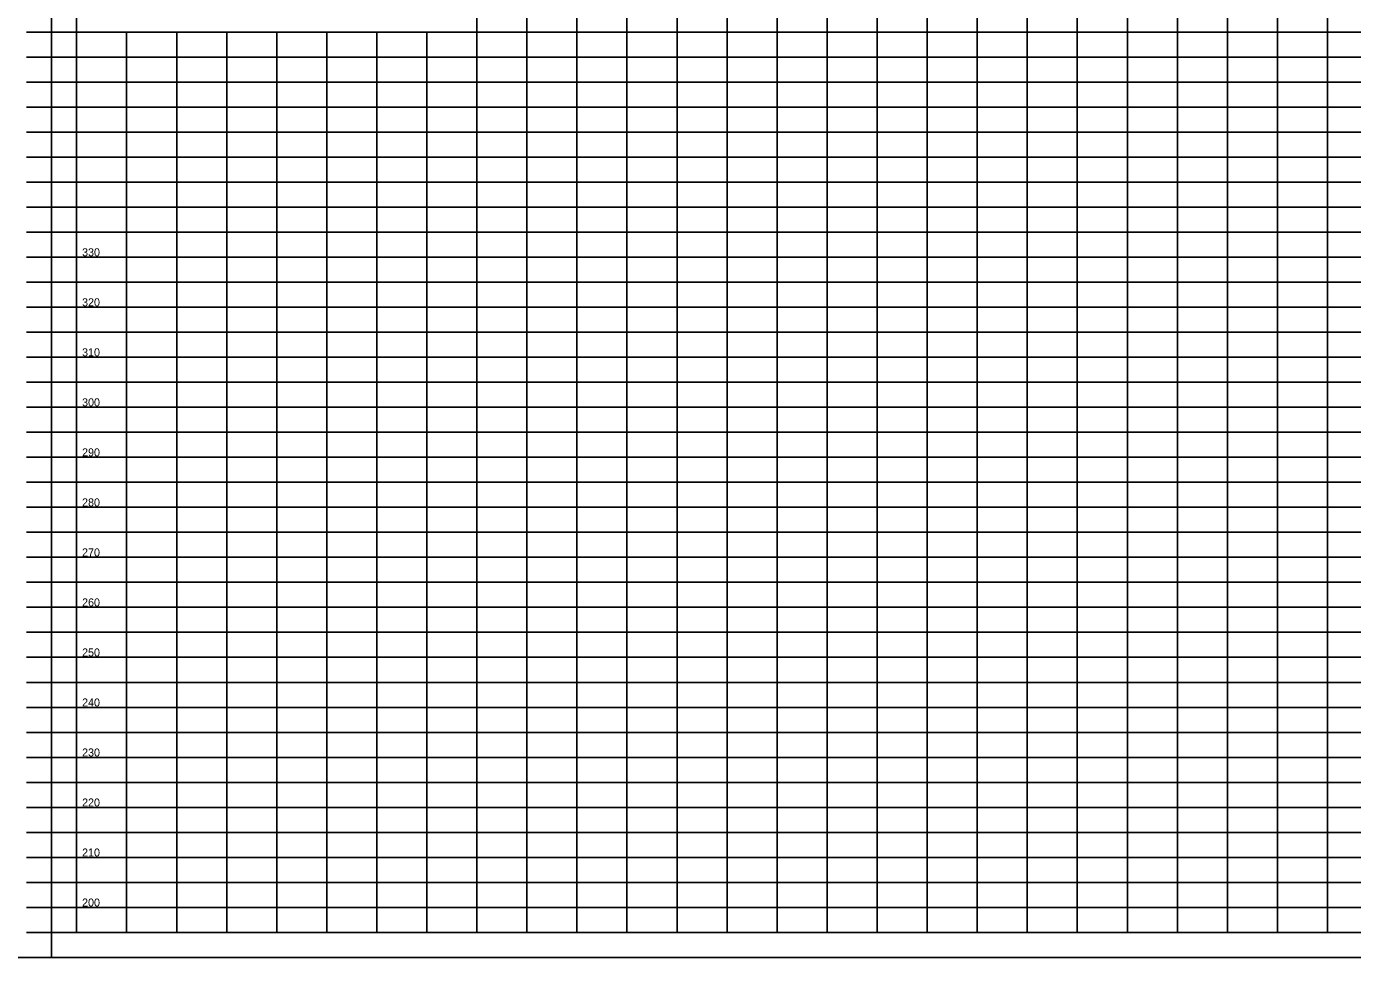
# Model space of a CAD drawing. Extents: x 1914168 to 1925341, y 720939 to 777401.
# Drawn here: x 1919832 to 1921157, y 735939 to 736870 of the extents above; entities that cross this region are included whole.
import ezdxf

# ---------------------------------------------------------------- set-up
doc = ezdxf.new("R2010")
doc.units = 0
for name, color, linetype in [('RD_DDB_ElevTX', 7, 'Continuous'), ('RD_PD_WallFill', 7, 'Continuous'), ('RD_SHT_IplotShp', 7, 'Continuous')]:
    doc.layers.add(name, color=color, linetype=linetype)

msp = doc.modelspace()

# ---------------------------------------------------------------- linework, layer by layer
at = {"layer": 'RD_PD_WallFill'}
for p, q in [((1919881.8, 735964.2), (1919881.8, 737014.2)), ((1919881.8, 735964.2), (1919881.8, 737014.2)), ((1920281.8, 735964.2), (1920281.8, 737014.2)), ((1920281.8, 735964.2), (1920281.8, 737014.2)), ((1920331.8, 735964.2), (1920331.8, 737014.2)), ((1920331.8, 735964.2), (1920331.8, 737014.2)), ((1920381.8, 735964.2), (1920381.8, 737014.2)), ((1920381.8, 735964.2), (1920381.8, 737014.2)), ((1920431.8, 735964.2), (1920431.8, 737014.2)), ((1920431.8, 735964.2), (1920431.8, 737014.2)), ((1920481.8, 735964.2), (1920481.8, 737014.2)), ((1920481.8, 735964.2), (1920481.8, 737014.2)), ((1920531.8, 735964.2), (1920531.8, 737014.2)), ((1920531.8, 735964.2), (1920531.8, 737014.2)), ((1920581.8, 735964.2), (1920581.8, 737014.2)), ((1920581.8, 735964.2), (1920581.8, 737014.2)), ((1920631.8, 735964.2), (1920631.8, 737014.2)), ((1920631.8, 735964.2), (1920631.8, 737014.2)), ((1920681.8, 735964.2), (1920681.8, 737014.2)), ((1920681.8, 735964.2), (1920681.8, 737014.2)), ((1920731.8, 735964.2), (1920731.8, 737014.2)), ((1920731.8, 735964.2), (1920731.8, 737014.2)), ((1920781.8, 735964.2), (1920781.8, 737014.2)), ((1920781.8, 735964.2), (1920781.8, 737014.2)), ((1920831.8, 735964.2), (1920831.8, 737014.2)), ((1920831.8, 735964.2), (1920831.8, 737014.2)), ((1920881.8, 735964.2), (1920881.8, 737014.2)), ((1920881.8, 735964.2), (1920881.8, 737014.2)), ((1920931.8, 735964.2), (1920931.8, 737014.2)), ((1920931.8, 735964.2), (1920931.8, 737014.2)), ((1920981.8, 735964.2), (1920981.8, 737014.2)), ((1920981.8, 735964.2), (1920981.8, 737014.2)), ((1921031.8, 735964.2), (1921031.8, 737014.2)), ((1921031.8, 735964.2), (1921031.8, 737014.2)), ((1921081.8, 735964.2), (1921081.8, 737014.2)), ((1921081.8, 735964.2), (1921081.8, 737014.2)), ((1921131.8, 735964.2), (1921131.8, 737014.2)), ((1921131.8, 735964.2), (1921131.8, 737014.2)), ((1919831.8, 736864.2), (1925181.8, 736864.2)), ((1919931.8, 735964.2), (1919931.8, 736864.2)), ((1919931.8, 735964.2), (1919931.8, 736864.2)), ((1919981.8, 735964.2), (1919981.8, 736864.2)), ((1919981.8, 735964.2), (1919981.8, 736864.2)), ((1920031.8, 735964.2), (1920031.8, 736864.2)), ((1920031.8, 735964.2), (1920031.8, 736864.2)), ((1920081.8, 735964.2), (1920081.8, 736864.2)), ((1920081.8, 735964.2), (1920081.8, 736864.2)), ((1920131.8, 735964.2), (1920131.8, 736864.2)), ((1920131.8, 735964.2), (1920131.8, 736864.2)), ((1920181.8, 735964.2), (1920181.8, 736864.2)), ((1920181.8, 735964.2), (1920181.8, 736864.2)), ((1920231.8, 735964.2), (1920231.8, 736864.2)), ((1920231.8, 735964.2), (1920231.8, 736864.2)), ((1919831.8, 736839.2), (1925181.8, 736839.2)), ((1919831.8, 736814.2), (1925181.8, 736814.2)), ((1919831.8, 736789.2), (1925181.8, 736789.2)), ((1919831.8, 736764.2), (1925181.8, 736764.2)), ((1919831.8, 736739.2), (1925181.8, 736739.2)), ((1919831.8, 736714.2), (1925181.8, 736714.2)), ((1919831.8, 736689.2), (1925181.8, 736689.2)), ((1919831.8, 736664.2), (1925181.8, 736664.2)), ((1919831.8, 736639.2), (1925181.8, 736639.2)), ((1919831.8, 736614.2), (1925181.8, 736614.2)), ((1919831.8, 736589.2), (1925181.8, 736589.2)), ((1919831.8, 736564.2), (1925181.8, 736564.2)), ((1919831.8, 736539.2), (1925181.8, 736539.2)), ((1919831.8, 736514.2), (1925181.8, 736514.2)), ((1919831.8, 736489.2), (1925181.8, 736489.2)), ((1919831.8, 736464.2), (1925181.8, 736464.2)), ((1919831.8, 736439.2), (1925181.8, 736439.2)), ((1919831.8, 736414.2), (1925181.8, 736414.2)), ((1919831.8, 736389.2), (1925181.8, 736389.2)), ((1919831.8, 736364.2), (1925181.8, 736364.2)), ((1919831.8, 736339.2), (1925181.8, 736339.2)), ((1919831.8, 736314.2), (1925181.8, 736314.2)), ((1919831.8, 736289.2), (1925181.8, 736289.2)), ((1919831.8, 736264.2), (1925181.8, 736264.2)), ((1919831.8, 736239.2), (1925181.8, 736239.2)), ((1919831.8, 736214.2), (1925181.8, 736214.2)), ((1919831.8, 736189.2), (1925181.8, 736189.2)), ((1919831.8, 736164.2), (1925181.8, 736164.2)), ((1919831.8, 736139.2), (1925181.8, 736139.2)), ((1919831.8, 736114.2), (1925181.8, 736114.2)), ((1919831.8, 736089.2), (1925181.8, 736089.2)), ((1919831.8, 736064.2), (1925181.8, 736064.2)), ((1919831.8, 736039.2), (1925181.8, 736039.2)), ((1919831.8, 736014.2), (1925181.8, 736014.2)), ((1919831.8, 735989.2), (1925181.8, 735989.2)), ((1919831.8, 735964.2), (1925181.8, 735964.2)), ((1919831.8, 735964.2), (1925181.8, 735964.2))]:
    msp.add_line(p, q, dxfattribs=at)
msp.add_lwpolyline([(1919881.8, 737014.2), (1920281.8, 737014.2), (1920281.8, 736864.2), (1919881.8, 736864.2)], close=True, dxfattribs=at)
msp.add_lwpolyline([(1919881.8, 737014.2), (1920281.8, 737014.2), (1920281.8, 736864.2), (1919881.8, 736864.2)], close=True, dxfattribs=at)
msp.add_lwpolyline([(1919881.8, 737014.2), (1920281.8, 737014.2), (1920281.8, 736864.2), (1919881.8, 736864.2)], close=True, dxfattribs=at)
msp.add_lwpolyline([(1919881.8, 737014.2), (1920281.8, 737014.2), (1920281.8, 736864.2), (1919881.8, 736864.2)], close=True, dxfattribs=at)
at = {"layer": 'RD_SHT_IplotShp'}
for points in [[(1914456.7, 735939.1), (1919856.7, 735939.1), (1919856.7, 737039.1), (1914456.7, 737039.1)], [(1919800.4, 735939.1), (1924000.4, 735939.1), (1924000.4, 737039.1), (1919800.4, 737039.1)]]:
    msp.add_lwpolyline(points, close=True, dxfattribs=at)

# ---------------------------------------------------------------- texts
at = {"layer": 'RD_DDB_ElevTX'}
for s, p in [('330', (1919887.3, 736640.1)), ('320', (1919887.3, 736590.1)), ('310', (1919887.3, 736540.1)), ('300', (1919887.3, 736490.1)), ('290', (1919887.3, 736440.1)), ('280', (1919887.3, 736390.1)), ('270', (1919887.3, 736340.1)), ('260', (1919887.3, 736290.1)), ('250', (1919887.3, 736240.1)), ('240', (1919887.3, 736190.1)), ('230', (1919887.3, 736140.1)), ('220', (1919887.3, 736090.1)), ('210', (1919887.3, 736040.1)), ('200', (1919887.3, 735990.1))]:
    msp.add_text(s, height=8, dxfattribs=at).set_placement(p)

doc.saveas('drawing.dxf')
